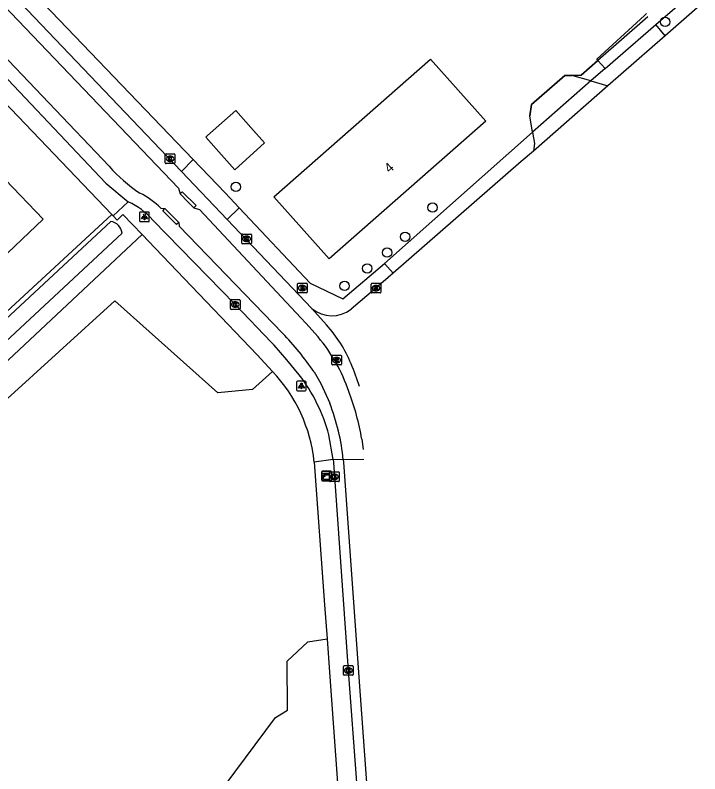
# Model space of a CAD drawing. Extents: x 156651 to 158072, y 387631 to 388990.
# Drawn here: x 157592.7 to 157663.6, y 388049.9 to 388128.4 of the extents above; entities that cross this region are included whole.
import ezdxf

# ---------------------------------------------------------------- set-up
doc = ezdxf.new("R2010")
doc.units = 0
for name, color, linetype in [('IMGEO_Boom', 7, 'Continuous'), ('IMGEO_Brandkraan', 7, 'Continuous'), ('IMGEO_Gemengd_bos', 7, 'Continuous'), ('IMGEO_Groenvoorziening', 7, 'Continuous'), ('IMGEO_Hek', 7, 'Continuous'), ('IMGEO_Kast', 7, 'Continuous'), ('IMGEO_Kolk', 7, 'Continuous'), ('IMGEO_Lichtpunt', 7, 'Continuous'), ('IMGEO_Muur', 7, 'Continuous'), ('IMGEO_Pand', 7, 'Continuous'), ('IMGEO_Pand_nummerreeks', 7, 'Continuous'), ('IMGEO_Rijbaan_lokaal_open', 7, 'Continuous'), ('IMGEO_Rioolput', 7, 'Continuous'), ('IMGEO_Voetpad_open', 7, 'Continuous'), ('IMGEO_Waterloop', 7, 'Continuous')]:
    doc.layers.add(name, color=color, linetype=linetype)

msp = doc.modelspace()

# ---------------------------------------------------------------- linework, layer by layer
at = {"layer": 'IMGEO_Boom'}
for centre in [(157659.961, 388127.657), (157615.557, 388110.603), (157635.902, 388108.46), (157633.062, 388105.443), (157631.197, 388103.814), (157629.139, 388102.167), (157626.792, 388100.368)]:
    msp.add_circle(centre, 0.489, dxfattribs=at)
at = {"layer": 'IMGEO_Brandkraan'}
for p, q in [((157621.934, 388099.721), (157621.934, 388100.573)), ((157622.009, 388100.647), (157622.861, 388100.647)), ((157622.422, 388100.427), (157622.447, 388100.427)), ((157622.935, 388100.573), (157622.935, 388099.721)), ((157622.861, 388099.647), (157622.009, 388099.647)), ((157622.445, 388099.867), (157622.42, 388099.867))]:
    msp.add_line(p, q, dxfattribs=at)
for points in [[(157621.934, 388099.721), (157621.934, 388100.573)], [(157622.009, 388100.647), (157622.861, 388100.647)], [(157622.282, 388100.347), (157622.282, 388099.947), (157622.495, 388099.947)], [(157622.513, 388100.347), (157622.282, 388100.347)], [(157622.461, 388100.266), (157622.407, 388100.266), (157622.407, 388100.19)], [(157622.407, 388100.19), (157622.46, 388100.19)], [(157622.469, 388100.114), (157622.407, 388100.114), (157622.407, 388100.033)], [(157622.407, 388100.033), (157622.469, 388100.033)], [(157622.935, 388100.573), (157622.935, 388099.721)], [(157622.861, 388099.647), (157622.009, 388099.647)]]:
    msp.add_lwpolyline(points, dxfattribs=at)
for centre, radius, start, end in [((157622.011, 388100.571), 0.0765, 91.55205, 178.44795), ((157622.011, 388100.571), 0.0765, 91.55205, 178.44795), ((157622.462, 388100.228), 0.0379, 267.82845, 90.93552), ((157622.47, 388100.073), 0.0404, 269.87594, 90.50774), ((157622.501, 388100.198), 0.251, 268.66757, 293.53466), ((157622.517, 388100.202), 0.145, 59.4692, 91.53667), ((157622.542, 388100.249), 0.0922, 285.51372, 58.15012), ((157622.547, 388100.057), 0.105, 301.31148, 78.98903), ((157622.859, 388100.571), 0.0765, 1.55205, 88.44795), ((157622.859, 388100.571), 0.0765, 1.55205, 88.44795), ((157622.011, 388099.723), 0.0765, 181.55205, 268.44795), ((157622.011, 388099.723), 0.0765, 181.55205, 268.44795), ((157622.859, 388099.723), 0.0765, 271.55205, 358.44795), ((157622.859, 388099.723), 0.0765, 271.55205, 358.44795)]:
    msp.add_arc(centre, radius, start, end, dxfattribs=at)
for centre, major_axis, ratio, start_param, end_param in [((157622.421, 388100.147), (-0.387, 0.002), 0.722429, 4.712389, 7.853982), ((157622.446, 388100.147), (-0.39, 0.002), 0.717154, 1.570796, 4.712389)]:
    msp.add_ellipse(centre, major_axis=major_axis, ratio=ratio, start_param=start_param, end_param=end_param, dxfattribs=at)
at = {"layer": 'IMGEO_Gemengd_bos'}
for points in [[(157617.824, 388043.477), (157568.335, 388010.487), (157551.976, 388000), (157551.233, 387999.524), (157548.86, 387998.003), (157547.263, 388000), (157521.408, 388032.33), (157543.243, 388052.841), (157602.721, 388107.759)], [(157619.33, 388091.512), (157617.29, 388089.65), (157613.671, 388089.32), (157603.045, 388098.834), (157591.502, 388088.329), (157583.999, 388083.451), (157583.148, 388084.42), (157605.841, 388105.68)], [(157617.824, 388043.477), (157614.435, 388048.767), (157619.655, 388055.738), (157620.91, 388056.517), (157620.87, 388061.577), (157622.996, 388063.579), (157624.989, 388063.89)]]:
    msp.add_lwpolyline(points, dxfattribs=at)
at = {"layer": 'IMGEO_Groenvoorziening'}
for points in [[(157659.964, 388126.225), (157659.013, 388127.388)], [(157650.311, 388122.132), (157651.289, 388122.149), (157653.016, 388123.661)], [(157653.756, 388122.838), (157652.287, 388121.55)], [(157630.946, 388102.684), (157646.249, 388116.257)], [(157611.15, 388113.418), (157611.903, 388112.641), (157611.955, 388112.587), (157614.435, 388109.985), (157615.908, 388108.421)]]:
    msp.add_lwpolyline(points, dxfattribs=at)
at = {"layer": 'IMGEO_Hek'}
for points in [[(157658.163, 388128.17), (157653.016, 388123.661)], [(157653.016, 388123.661), (157651.289, 388122.149), (157650.311, 388122.132)], [(157650.311, 388122.132), (157649.581, 388122.12), (157646.127, 388119.108), (157645.954, 388117.932)], [(157543.243, 388052.841), (157602.721, 388107.759)]]:
    msp.add_lwpolyline(points, dxfattribs=at)
at = {"layer": 'IMGEO_Kast'}
for p, q in [((157624.44, 388080.289), (157624.44, 388081.13)), ((157624.44, 388081.13), (157624.44, 388080.289)), ((157624.515, 388081.214), (157625.356, 388081.214)), ((157625.356, 388081.214), (157624.515, 388081.214)), ((157625.44, 388081.139), (157625.44, 388080.298)), ((157625.44, 388080.298), (157625.44, 388081.139)), ((157625.365, 388080.214), (157624.524, 388080.214)), ((157624.524, 388080.214), (157625.365, 388080.214))]:
    msp.add_line(p, q, dxfattribs=at)
for points in [[(157624.635, 388081.004), (157625.235, 388081.004), (157625.235, 388080.919), (157624.635, 388080.919), (157624.635, 388081.004)], [(157624.635, 388080.829), (157625.235, 388080.829), (157625.235, 388080.34), (157624.635, 388080.34), (157624.635, 388080.829)]]:
    msp.add_lwpolyline(points, dxfattribs=at)
msp.add_circle((157624.719, 388080.678), 0.0377, dxfattribs=at)
for centre, start, end in [((157624.518, 388081.136), 92.4484, 184.28452), ((157624.518, 388081.136), 92.4484, 184.28452), ((157625.362, 388081.136), 2.4484, 94.28452), ((157625.362, 388081.136), 2.4484, 94.28452), ((157624.518, 388080.292), 182.4484, 274.28452), ((157624.518, 388080.292), 182.4484, 274.28452), ((157625.362, 388080.292), 272.4484, 4.28452), ((157625.362, 388080.292), 272.4484, 4.28452)]:
    msp.add_arc(centre, 0.0779, start, end, dxfattribs=at)
at = {"layer": 'IMGEO_Kolk'}
for p, q in [((157608.326, 388114.011), (157609.178, 388114.011)), ((157608.251, 388113.085), (157608.251, 388113.937)), ((157608.762, 388113.231), (157608.737, 388113.231)), ((157608.739, 388113.791), (157608.764, 388113.791)), ((157609.252, 388113.937), (157609.252, 388113.085)), ((157609.178, 388113.011), (157608.326, 388113.011)), ((157616.162, 388104.794), (157616.162, 388105.646)), ((157616.237, 388105.72), (157617.089, 388105.72)), ((157616.65, 388105.5), (157616.675, 388105.5)), ((157617.163, 388105.646), (157617.163, 388104.794)), ((157617.089, 388104.72), (157616.237, 388104.72)), ((157616.673, 388104.94), (157616.648, 388104.94)), ((157629.549, 388099.706), (157629.549, 388100.558)), ((157629.624, 388100.632), (157630.476, 388100.632)), ((157630.037, 388100.412), (157630.062, 388100.412)), ((157630.55, 388100.558), (157630.55, 388099.706)), ((157630.476, 388099.632), (157629.624, 388099.632)), ((157630.06, 388099.852), (157630.035, 388099.852)), ((157614.985, 388098.016), (157614.985, 388098.868)), ((157615.06, 388098.942), (157615.912, 388098.942)), ((157615.473, 388098.722), (157615.498, 388098.722)), ((157615.986, 388098.868), (157615.986, 388098.016)), ((157615.912, 388097.942), (157615.06, 388097.942)), ((157615.496, 388098.162), (157615.471, 388098.162)), ((157625.245, 388080.207), (157625.245, 388081.059)), ((157625.32, 388081.133), (157626.172, 388081.133)), ((157626.246, 388081.059), (157626.246, 388080.207)), ((157625.756, 388080.353), (157625.731, 388080.353)), ((157625.733, 388080.913), (157625.758, 388080.913)), ((157626.172, 388080.133), (157625.32, 388080.133)), ((157626.684, 388060.18), (157626.684, 388061.032)), ((157626.759, 388061.106), (157627.611, 388061.106)), ((157627.172, 388060.886), (157627.197, 388060.886)), ((157627.685, 388061.032), (157627.685, 388060.18)), ((157627.611, 388060.106), (157626.759, 388060.106)), ((157627.195, 388060.326), (157627.17, 388060.326))]:
    msp.add_line(p, q, dxfattribs=at)
for points in [[(157608.326, 388114.011), (157609.178, 388114.011)], [(157608.251, 388113.085), (157608.251, 388113.937)], [(157608.572, 388113.711), (157608.695, 388113.711), (157608.695, 388113.56), (157608.825, 388113.711), (157608.989, 388113.711), (157608.843, 388113.56), (157608.996, 388113.311), (157608.844, 388113.311), (157608.759, 388113.475), (157608.695, 388113.408), (157608.695, 388113.311), (157608.572, 388113.311), (157608.572, 388113.711)], [(157609.252, 388113.937), (157609.252, 388113.085)], [(157609.178, 388113.011), (157608.326, 388113.011)], [(157616.162, 388104.794), (157616.162, 388105.646)], [(157616.237, 388105.72), (157617.089, 388105.72)], [(157616.483, 388105.42), (157616.606, 388105.42), (157616.606, 388105.269), (157616.736, 388105.42), (157616.9, 388105.42), (157616.754, 388105.269), (157616.907, 388105.02), (157616.755, 388105.02), (157616.67, 388105.184), (157616.606, 388105.117), (157616.606, 388105.02), (157616.483, 388105.02), (157616.483, 388105.42)], [(157617.163, 388105.646), (157617.163, 388104.794)], [(157617.089, 388104.72), (157616.237, 388104.72)], [(157629.549, 388099.706), (157629.549, 388100.558)], [(157629.624, 388100.632), (157630.476, 388100.632)], [(157629.87, 388100.332), (157629.993, 388100.332), (157629.993, 388100.181), (157630.123, 388100.332), (157630.287, 388100.332), (157630.141, 388100.181), (157630.294, 388099.932), (157630.142, 388099.932), (157630.057, 388100.096), (157629.993, 388100.029), (157629.993, 388099.932), (157629.87, 388099.932), (157629.87, 388100.332)], [(157630.55, 388100.558), (157630.55, 388099.706)], [(157630.476, 388099.632), (157629.624, 388099.632)], [(157614.985, 388098.016), (157614.985, 388098.868)], [(157615.06, 388098.942), (157615.912, 388098.942)], [(157615.306, 388098.642), (157615.429, 388098.642), (157615.429, 388098.491), (157615.559, 388098.642), (157615.723, 388098.642), (157615.577, 388098.491), (157615.73, 388098.242), (157615.578, 388098.242), (157615.493, 388098.406), (157615.429, 388098.339), (157615.429, 388098.242), (157615.306, 388098.242), (157615.306, 388098.642)], [(157615.986, 388098.868), (157615.986, 388098.016)], [(157615.912, 388097.942), (157615.06, 388097.942)], [(157625.245, 388080.207), (157625.245, 388081.059)], [(157625.32, 388081.133), (157626.172, 388081.133)], [(157626.246, 388081.059), (157626.246, 388080.207)], [(157625.566, 388080.833), (157625.689, 388080.833), (157625.689, 388080.682), (157625.819, 388080.833), (157625.983, 388080.833), (157625.837, 388080.682), (157625.99, 388080.433), (157625.838, 388080.433), (157625.753, 388080.597), (157625.689, 388080.53), (157625.689, 388080.433), (157625.566, 388080.433), (157625.566, 388080.833)], [(157626.172, 388080.133), (157625.32, 388080.133)], [(157626.684, 388060.18), (157626.684, 388061.032)], [(157626.759, 388061.106), (157627.611, 388061.106)], [(157627.005, 388060.806), (157627.128, 388060.806), (157627.128, 388060.655), (157627.258, 388060.806), (157627.422, 388060.806), (157627.276, 388060.655), (157627.429, 388060.406), (157627.277, 388060.406), (157627.192, 388060.57), (157627.128, 388060.503), (157627.128, 388060.406), (157627.005, 388060.406), (157627.005, 388060.806)], [(157627.685, 388061.032), (157627.685, 388060.18)], [(157627.611, 388060.106), (157626.759, 388060.106)]]:
    msp.add_lwpolyline(points, dxfattribs=at)
for centre, start, end in [((157608.328, 388113.935), 91.55205, 178.44795), ((157608.328, 388113.935), 91.55205, 178.44795), ((157609.176, 388113.935), 1.55205, 88.44795), ((157609.176, 388113.935), 1.55205, 88.44795), ((157608.328, 388113.087), 181.55205, 268.44795), ((157608.328, 388113.087), 181.55205, 268.44795), ((157609.176, 388113.087), 271.55205, 358.44795), ((157609.176, 388113.087), 271.55205, 358.44795), ((157616.239, 388105.644), 91.55205, 178.44795), ((157616.239, 388105.644), 91.55205, 178.44795), ((157617.087, 388105.644), 1.55205, 88.44795), ((157617.087, 388105.644), 1.55205, 88.44795), ((157616.239, 388104.796), 181.55205, 268.44795), ((157616.239, 388104.796), 181.55205, 268.44795), ((157617.087, 388104.796), 271.55205, 358.44795), ((157617.087, 388104.796), 271.55205, 358.44795), ((157629.626, 388100.556), 91.55205, 178.44795), ((157629.626, 388100.556), 91.55205, 178.44795), ((157630.474, 388100.556), 1.55205, 88.44795), ((157630.474, 388100.556), 1.55205, 88.44795), ((157629.626, 388099.708), 181.55205, 268.44795), ((157629.626, 388099.708), 181.55205, 268.44795), ((157630.474, 388099.708), 271.55205, 358.44795), ((157630.474, 388099.708), 271.55205, 358.44795), ((157615.062, 388098.866), 91.55205, 178.44795), ((157615.062, 388098.866), 91.55205, 178.44795), ((157615.91, 388098.866), 1.55205, 88.44795), ((157615.91, 388098.866), 1.55205, 88.44795), ((157615.062, 388098.018), 181.55205, 268.44795), ((157615.062, 388098.018), 181.55205, 268.44795), ((157615.91, 388098.018), 271.55205, 358.44795), ((157615.91, 388098.018), 271.55205, 358.44795), ((157625.322, 388081.057), 91.55205, 178.44795), ((157625.322, 388081.057), 91.55205, 178.44795), ((157626.17, 388081.057), 1.55205, 88.44795), ((157626.17, 388081.057), 1.55205, 88.44795), ((157625.322, 388080.209), 181.55205, 268.44795), ((157625.322, 388080.209), 181.55205, 268.44795), ((157626.17, 388080.209), 271.55205, 358.44795), ((157626.17, 388080.209), 271.55205, 358.44795), ((157626.761, 388061.03), 91.55205, 178.44795), ((157626.761, 388061.03), 91.55205, 178.44795), ((157627.609, 388061.03), 1.55205, 88.44795), ((157627.609, 388061.03), 1.55205, 88.44795), ((157626.761, 388060.182), 181.55205, 268.44795), ((157626.761, 388060.182), 181.55205, 268.44795), ((157627.609, 388060.182), 271.55205, 358.44795), ((157627.609, 388060.182), 271.55205, 358.44795)]:
    msp.add_arc(centre, 0.0765, start, end, dxfattribs=at)
for centre, major_axis, ratio, start_param, end_param in [((157608.738, 388113.511), (-0.387, 0.002), 0.722429, 4.712389, 7.853982), ((157608.763, 388113.511), (-0.39, 0.002), 0.717154, 1.570796, 4.712389), ((157616.649, 388105.22), (-0.387, 0.002), 0.722429, 4.712389, 7.853982), ((157616.674, 388105.22), (-0.39, 0.002), 0.717154, 1.570796, 4.712389), ((157630.036, 388100.132), (-0.387, 0.002), 0.722429, 4.712389, 7.853982), ((157630.061, 388100.132), (-0.39, 0.002), 0.717154, 1.570796, 4.712389), ((157615.472, 388098.442), (-0.387, 0.002), 0.722429, 4.712389, 7.853982), ((157615.497, 388098.442), (-0.39, 0.002), 0.717154, 1.570796, 4.712389), ((157625.732, 388080.633), (-0.387, 0.002), 0.722429, 4.712389, 7.853982), ((157625.757, 388080.633), (-0.39, 0.002), 0.717154, 1.570796, 4.712389), ((157627.171, 388060.606), (-0.387, 0.002), 0.722429, 4.712389, 7.853982), ((157627.196, 388060.606), (-0.39, 0.002), 0.717154, 1.570796, 4.712389)]:
    msp.add_ellipse(centre, major_axis=major_axis, ratio=ratio, start_param=start_param, end_param=end_param, dxfattribs=at)
at = {"layer": 'IMGEO_Lichtpunt'}
for p, q in [((157605.599, 388107.909), (157605.599, 388107.102)), ((157605.599, 388107.909), (157605.599, 388107.102)), ((157606.501, 388108.004), (157605.693, 388108.004)), ((157606.501, 388108.004), (157605.693, 388108.004)), ((157606.595, 388107.102), (157606.595, 388107.909)), ((157606.595, 388107.102), (157606.595, 388107.909)), ((157605.693, 388107.008), (157606.501, 388107.008)), ((157605.693, 388107.008), (157606.501, 388107.008)), ((157622.73, 388090.52), (157621.922, 388090.52)), ((157622.73, 388090.52), (157621.922, 388090.52)), ((157621.828, 388090.425), (157621.828, 388089.618)), ((157621.828, 388090.425), (157621.828, 388089.618)), ((157622.824, 388089.618), (157622.824, 388090.425)), ((157622.824, 388089.618), (157622.824, 388090.425)), ((157621.922, 388089.524), (157622.73, 388089.524)), ((157621.922, 388089.524), (157622.73, 388089.524))]:
    msp.add_line(p, q, dxfattribs=at)
for points in [[(157605.973, 388107.573), (157606.012, 388107.545), (157605.824, 388107.283), (157605.786, 388107.31), (157605.973, 388107.573)], [(157606.075, 388107.525), (157606.122, 388107.525), (157606.122, 388107.203), (157606.075, 388107.203), (157606.075, 388107.525)], [(157606.185, 388107.545), (157606.223, 388107.572), (157606.41, 388107.31), (157606.371, 388107.282), (157606.185, 388107.545)], [(157622.202, 388090.089), (157622.241, 388090.061), (157622.053, 388089.799), (157622.015, 388089.826), (157622.202, 388090.089)], [(157622.304, 388090.041), (157622.351, 388090.041), (157622.351, 388089.719), (157622.304, 388089.719), (157622.304, 388090.041)], [(157622.414, 388090.061), (157622.452, 388090.088), (157622.639, 388089.826), (157622.6, 388089.798), (157622.414, 388090.061)]]:
    msp.add_lwpolyline(points, dxfattribs=at)
for centre in [(157606.098, 388107.707), (157622.327, 388090.223)]:
    msp.add_circle(centre, 0.0994, dxfattribs=at)
for centre, start, end in [((157605.693, 388107.909), 90, 180), ((157605.693, 388107.909), 90, 180), ((157606.501, 388107.909), 0, 90), ((157606.501, 388107.909), 0, 90), ((157605.693, 388107.102), 180, 270), ((157605.693, 388107.102), 180, 270), ((157606.501, 388107.102), 270, 0), ((157606.501, 388107.102), 270, 360), ((157621.922, 388090.425), 90, 180), ((157621.922, 388090.425), 90, 180), ((157622.73, 388090.425), 0, 90), ((157622.73, 388090.425), 0, 90), ((157621.922, 388089.618), 180, 270), ((157621.922, 388089.618), 180, 270), ((157622.73, 388089.618), 270, 0), ((157622.73, 388089.618), 270, 360)]:
    msp.add_arc(centre, 0.0946, start, end, dxfattribs=at)
at = {"layer": 'IMGEO_Muur'}
for points in [[(157609.788, 388109.895), (157609.989, 388110.099), (157611.432, 388108.678), (157611.207, 388108.452)], [(157611.207, 388108.452), (157610.633, 388109.036), (157609.788, 388109.895)], [(157609.641, 388106.929), (157609.418, 388106.701), (157607.979, 388108.127), (157608.205, 388108.355)], [(157608.205, 388108.355), (157609.641, 388106.932), (157609.641, 388106.929)]]:
    msp.add_lwpolyline(points, dxfattribs=at)
at = {"layer": 'IMGEO_Pand'}
for points in [[(157641.414, 388117.38), (157625.189, 388103.157), (157619.496, 388109.575), (157635.703, 388123.804), (157641.414, 388117.38)], [(157615.534, 388118.501), (157617.106, 388116.735), (157618.517, 388115.15), (157615.438, 388112.364), (157614.055, 388113.931), (157612.447, 388115.753), (157612.63, 388115.916), (157615.534, 388118.501)], [(157591.735, 388111.337), (157590.578, 388110.215), (157587.266, 388113.685), (157585.136, 388115.916), (157581.948, 388112.886), (157577.742, 388117.319), (157564.772, 388104.959), (157568.98, 388100.543), (157572.815, 388104.198), (157574.655, 388102.268), (157579.435, 388106.824), (157585.633, 388100.32), (157589.181, 388103.702), (157590.457, 388102.362), (157595.605, 388107.266), (157591.735, 388111.337)]]:
    msp.add_lwpolyline(points, dxfattribs=at)
at = {"layer": 'IMGEO_Rijbaan_lokaal_open'}
for points in [[(157505.252, 388219.445), (157569.611, 388152.266), (157609.631, 388110.47), (157609.788, 388109.895)], [(157502.666, 388217.076), (157520.881, 388198.047), (157571.193, 388145.504), (157602.434, 388112.73)], [(157729.533, 388188.285), (157726.48, 388185.589), (157719.501, 388179.05), (157705.796, 388166.305), (157703.948, 388164.689), (157659.964, 388126.225)], [(157609.911, 388112.196), (157591.786, 388131.202), (157577.621, 388146.005), (157573.012, 388150.836), (157569.341, 388154.667), (157564.008, 388160.23)], [(157659.964, 388126.225), (157654.031, 388121.036)], [(157588.386, 388125.454), (157602.101, 388110.987), (157604.416, 388109.059)], [(157646.249, 388116.257), (157645.954, 388117.932), (157646.127, 388119.108), (157649.581, 388122.12), (157650.311, 388122.132)], [(157652.287, 388121.55), (157650.311, 388122.132)], [(157652.287, 388121.55), (157646.249, 388116.257)], [(157652.287, 388121.55), (157654.031, 388121.036)], [(157654.031, 388121.036), (157646.329, 388114.301)], [(157646.249, 388116.257), (157646.454, 388115.097), (157646.329, 388114.301)], [(157646.329, 388114.301), (157645.085, 388113.213), (157631.831, 388101.666)], [(157614.66, 388107.216), (157609.911, 388112.196)], [(157607.788, 388108.401), (157608.205, 388108.355)], [(157611.207, 388108.452), (157611.22, 388108.439), (157611.799, 388108.253), (157622.266, 388097.074), (157622.801, 388096.503), (157624.063, 388095.085)], [(157622.099, 388091.175), (157620.833, 388092.727), (157619.517, 388094.245), (157619.255, 388094.518), (157615.487, 388098.443), (157606.976, 388107.174)], [(157623.408, 388098.043), (157614.66, 388107.216)], [(157609.641, 388106.929), (157609.691, 388106.528), (157620.38, 388095.484)], [(157631.831, 388101.666), (157630.049, 388100.133), (157627.477, 388097.962)], [(157624.93, 388096.337), (157623.408, 388098.043)], [(157623.646, 388091.476), (157624.328, 388090.29), (157625.259, 388088.225)], [(157625.617, 388082.408), (157625.177, 388084.972)], [(157628.577, 388084.514), (157628.728, 388083.446)], [(157626.67, 388082.386), (157625.617, 388082.408)], [(157625.617, 388082.408), (157625.649, 388082.108), (157625.747, 388080.633), (157627.187, 388060.606), (157628.878, 388037.453), (157628.892, 388036.942)], [(157628.788, 388082.423), (157626.67, 388082.386)], [(157626.67, 388082.386), (157626.673, 388082.152), (157628.231, 388060.388), (157631.368, 388017.187), (157632.02, 388009.07), (157632.319, 388005.936), (157632.839, 388001.765), (157633.123, 388000), (157633.473, 387997.823), (157634.096, 387995.205), (157634.191, 387994.819)]]:
    msp.add_lwpolyline(points, dxfattribs=at)
for centre, radius, start, end in [((157615.745, 388124.759), 17.941, 222.10483, 235.60511), ((157602.175, 388102.837), 7.904, 44.74738, 64.23701), ((157601.16, 388101.957), 7.813, 41.89609, 65.37339), ((157625.493, 388100.537), 3.251, 230.10747, 307.6117), ((157614.53, 388086.942), 14.015, 22.51715, 42.09513), ((157596.575, 388072.752), 32.915, 34.67105, 43.68008), ((157610.663, 388083.841), 17.492, 18.69755, 39.99865), ((157590.562, 388077.271), 39.861, 18.58232, 22.16484), ((157607.919, 388080.274), 17.886, 15.22941, 37.55286), ((157604.3, 388080.548), 24.598, 9.27748, 21.21311), ((157605.01, 388080.242), 21.766, 5.65352, 21.51677)]:
    msp.add_arc(centre, radius, start, end, dxfattribs=at)
at = {"layer": 'IMGEO_Rioolput'}
for p, q in [((157625.475, 388092.268), (157625.475, 388093.12)), ((157625.55, 388093.194), (157626.402, 388093.194)), ((157625.963, 388092.974), (157625.988, 388092.974)), ((157626.476, 388093.12), (157626.476, 388092.268)), ((157626.402, 388092.194), (157625.55, 388092.194)), ((157625.986, 388092.414), (157625.961, 388092.414))]:
    msp.add_line(p, q, dxfattribs=at)
for points in [[(157625.475, 388092.268), (157625.475, 388093.12)], [(157625.55, 388093.194), (157626.402, 388093.194)], [(157626.064, 388092.892), (157625.812, 388092.894), (157625.812, 388092.494)], [(157626.476, 388093.12), (157626.476, 388092.268)], [(157626.402, 388092.194), (157625.55, 388092.194)], [(157625.812, 388092.494), (157625.936, 388092.494), (157625.936, 388092.656), (157625.947, 388092.656)], [(157625.99, 388092.813), (157625.936, 388092.813), (157625.936, 388092.732)], [(157625.936, 388092.732), (157625.988, 388092.732)], [(157625.994, 388092.627), (157626.065, 388092.494), (157626.205, 388092.494), (157626.14, 388092.62)]]:
    msp.add_lwpolyline(points, dxfattribs=at)
for centre, radius, start, end in [((157625.552, 388093.118), 0.0765, 91.55205, 178.44795), ((157625.552, 388093.118), 0.0765, 91.55205, 178.44795), ((157626.063, 388092.782), 0.109, 350.36119, 89.41601), ((157626.4, 388093.118), 0.0765, 1.55205, 88.44795), ((157626.4, 388093.118), 0.0765, 1.55205, 88.44795), ((157625.552, 388092.27), 0.0765, 181.55205, 268.44795), ((157625.552, 388092.27), 0.0765, 181.55205, 268.44795), ((157625.946, 388092.603), 0.0533, 26.02933, 88.69889), ((157625.972, 388092.921), 0.19, 274.7715, 282.96867), ((157625.996, 388092.717), 0.0964, 77.00612, 93.18647), ((157626.01, 388092.774), 0.0378, 276.66336, 79.67722), ((157626.061, 388092.782), 0.112, 277.58423, 350.98172), ((157626.045, 388092.567), 0.108, 29.51342, 73.79051), ((157626.4, 388092.27), 0.0765, 271.55205, 358.44795), ((157626.4, 388092.27), 0.0765, 271.55205, 358.44795)]:
    msp.add_arc(centre, radius, start, end, dxfattribs=at)
for centre, major_axis, ratio, start_param, end_param in [((157625.962, 388092.694), (-0.387, 0.002), 0.722429, 4.712389, 7.853982), ((157625.987, 388092.694), (-0.39, 0.002), 0.717154, 1.570796, 4.712389)]:
    msp.add_ellipse(centre, major_axis=major_axis, ratio=ratio, start_param=start_param, end_param=end_param, dxfattribs=at)
at = {"layer": 'IMGEO_Voetpad_open'}
for points in [[(157565.368, 388161.238), (157570.562, 388155.83), (157572.789, 388153.497), (157573.82, 388152.417), (157574.214, 388152.004), (157593.208, 388132.152), (157609.438, 388115.184), (157611.15, 388113.418)], [(157602.721, 388107.759), (157587.035, 388124.121)], [(157609.911, 388112.196), (157611.15, 388113.418)], [(157604.416, 388109.059), (157602.875, 388107.598)], [(157602.875, 388107.598), (157602.721, 388107.759)], [(157602.875, 388107.598), (157603.286, 388107.175), (157603.869, 388107.738), (157605.841, 388105.68)], [(157615.908, 388108.421), (157614.66, 388107.216)], [(157615.908, 388108.421), (157623.222, 388100.654), (157626.628, 388099.019), (157630.946, 388102.684)], [(157605.841, 388105.68), (157607.197, 388104.265), (157617.757, 388093.246), (157619.33, 388091.512)], [(157631.831, 388101.666), (157630.946, 388102.684)], [(157625.617, 388082.408), (157623.663, 388082.153)], [(157623.663, 388082.153), (157624.738, 388067.383), (157624.989, 388063.89)], [(157624.989, 388063.89), (157625.236, 388060.439), (157626.073, 388048.976)]]:
    msp.add_lwpolyline(points, dxfattribs=at)
msp.add_arc((157607.769, 388080.477), 15.982, 6.01945, 43.66663, dxfattribs=at)
at = {"layer": 'IMGEO_Waterloop'}
for points in [[(157659.013, 388127.388), (157662.185, 388130.133)], [(157653.016, 388123.661), (157652.893, 388123.798), (157657.812, 388128.327), (157658.038, 388128.535)], [(157653.756, 388122.838), (157659.013, 388127.388)], [(157653.016, 388123.661), (157653.756, 388122.838)], [(157602.616, 388107.038), (157548.714, 388056.963), (157543.847, 388052.069)], [(157544.916, 388050.869), (157549.479, 388055.298), (157603.784, 388105.825)]]:
    msp.add_lwpolyline(points, dxfattribs=at)
msp.add_arc((157602.354, 388105.617), 1.446, 8.29306, 79.54146, dxfattribs=at)

# ---------------------------------------------------------------- texts
at = {"layer": 'IMGEO_Pand_nummerreeks'}
msp.add_text('4', height=1, rotation=41.23813, dxfattribs=at).set_placement((157631.434, 388111.982))

doc.saveas('drawing.dxf')
